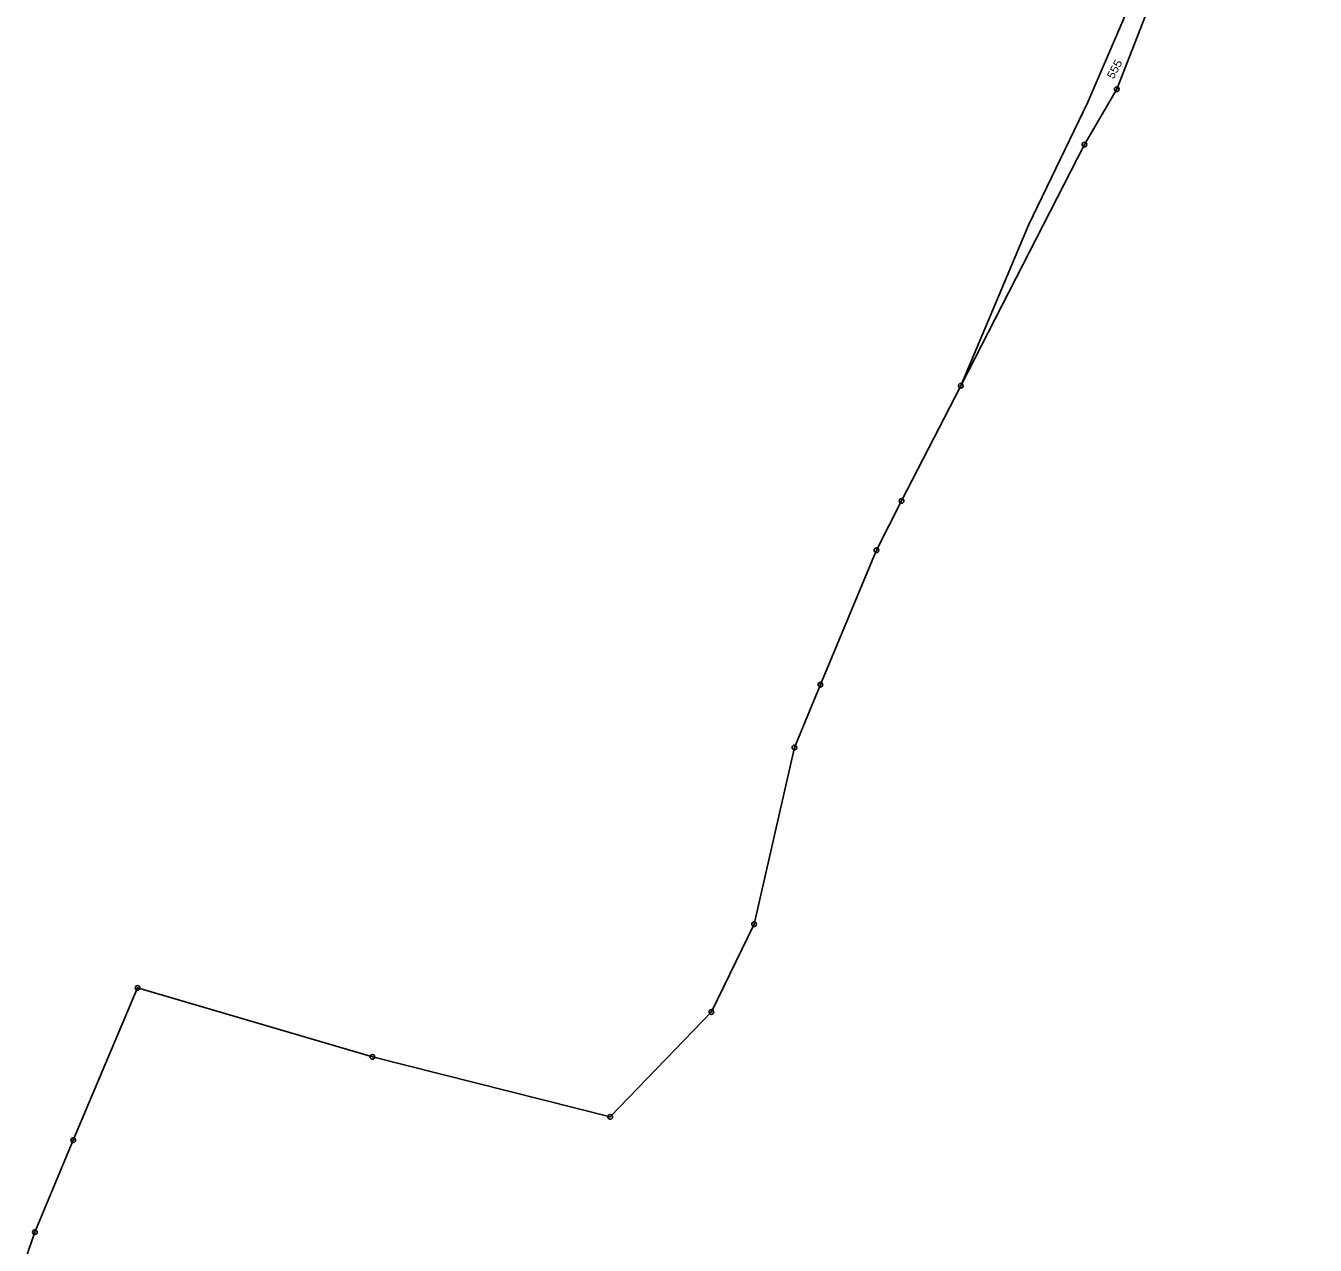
# Model space of a CAD drawing. Extents: x -885985 to -883535, y -1030025 to -1027941.
# Drawn here: x -884218.2 to -883944.3, y -1029584.6 to -1029325.6 of the extents above; entities that cross this region are included whole.
import ezdxf

# ---------------------------------------------------------------- set-up
doc = ezdxf.new("R2010")
doc.units = 0
doc.header["$LTSCALE"] = 0.68
doc.layers.add('1', color=7, linetype='Continuous', lineweight=25)
doc.layers.add('8', color=7, linetype='Continuous', lineweight=25)
doc.layers.add('2', color=7, linetype='Continuous')

msp = doc.modelspace()

# ---------------------------------------------------------------- linework, layer by layer
at = {"layer": '1'}
for p, q in [((-883944.29, -1029231.3), (-883986.44, -1029339.09)), ((-883978.21, -1029308.5), (-883992.6, -1029341.82)), ((-883993.32, -1029350.85), (-883986.44, -1029339.09)), ((-884005.23, -1029367.98), (-883992.6, -1029341.82)), ((-884019.6, -1029402.07), (-883993.32, -1029350.85)), ((-884005.23, -1029367.98), (-884019.6, -1029402.07)), ((-884032.18, -1029426.51), (-884019.6, -1029402.07)), ((-884037.51, -1029436.99), (-884032.18, -1029426.51)), ((-884049.41, -1029465.54), (-884037.51, -1029436.99)), ((-884054.92, -1029478.87), (-884049.41, -1029465.54)), ((-884054.92, -1029478.87), (-884063.51, -1029516.42)), ((-884063.51, -1029516.42), (-884072.57, -1029535.05)), ((-884208.14, -1029562.3), (-884194.47, -1029529.94)), ((-884144.57, -1029544.59), (-884194.47, -1029529.94)), ((-884072.57, -1029535.05), (-884094.07, -1029557.33)), ((-884094.07, -1029557.33), (-884144.57, -1029544.59)), ((-884216.27, -1029581.8), (-884208.14, -1029562.3)), ((-884218.22, -1029587.35), (-884216.27, -1029581.8))]:
    msp.add_line(p, q, dxfattribs=at)
at = {"layer": '8'}
for centre, radius in [((-883986.44, -1029339.0899), 0.5), ((-883986.44, -1029339.0899), 0.0303), ((-883993.32, -1029350.8499), 0.5), ((-883993.32, -1029350.8499), 0.0303), ((-884019.6, -1029402.0699), 0.5), ((-884019.6, -1029402.0699), 0.0303), ((-884032.18, -1029426.5099), 0.5), ((-884032.18, -1029426.5099), 0.0303), ((-884037.51, -1029436.9899), 0.5), ((-884037.51, -1029436.9899), 0.0303), ((-884049.41, -1029465.5399), 0.5), ((-884049.41, -1029465.5399), 0.0303), ((-884054.92, -1029478.8699), 0.5), ((-884054.92, -1029478.8699), 0.0303), ((-884063.51, -1029516.4199), 0.5), ((-884063.51, -1029516.4199), 0.0303), ((-884194.47, -1029529.9399), 0.5), ((-884194.47, -1029529.9399), 0.0303), ((-884072.57, -1029535.0499), 0.5), ((-884072.57, -1029535.0499), 0.0303), ((-884144.57, -1029544.5899), 0.5), ((-884144.57, -1029544.5899), 0.0303), ((-884094.07, -1029557.3299), 0.5), ((-884094.07, -1029557.3299), 0.0303), ((-884208.14, -1029562.2999), 0.5), ((-884208.14, -1029562.2999), 0.0303), ((-884216.27, -1029581.7999), 0.5), ((-884216.27, -1029581.7999), 0.0303)]:
    msp.add_circle(centre, radius, dxfattribs=at)

# ---------------------------------------------------------------- texts
at = {"layer": '2', "width": 1.1}
msp.add_text('555', height=1.7, rotation=62, dxfattribs=at).set_placement((-883987.144, -1029337.079))

doc.saveas('drawing.dxf')
